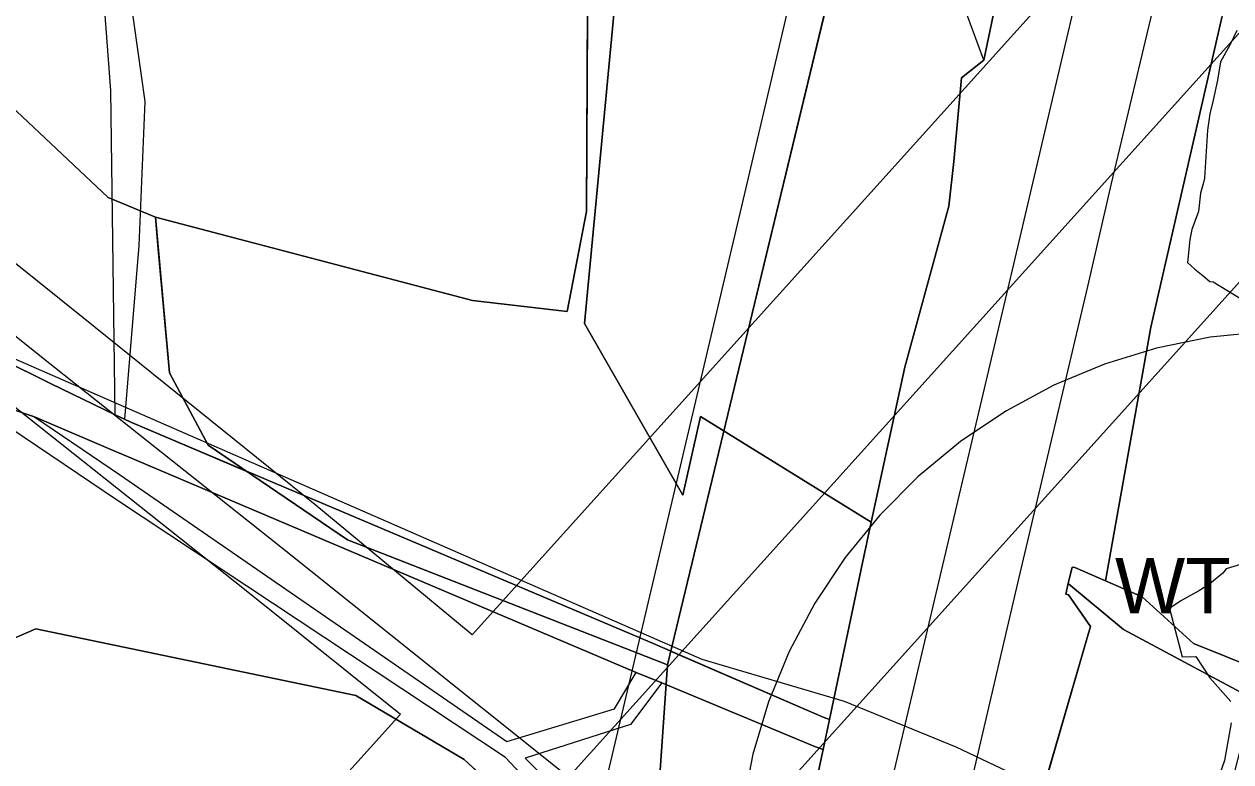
# Model space of a CAD drawing. Extents: x -690419 to -685080, y -987825 to -981190.
# Drawn here: x -687048.1 to -686831.2, y -987168.9 to -987036.3 of the extents above; entities that cross this region are included whole.
import ezdxf

# ---------------------------------------------------------------- set-up
doc = ezdxf.new("R2010")
doc.units = 0
for name, color, linetype in [('BP VTL plynovodu a RS (S)', 7, 'Continuous'), ('BPEJ (S) - hranice', 7, 'Continuous'), ('BPEJ I-II ochrana', 7, 'Continuous'), ('Elektro VN 35 nadzemní (S)', 7, 'Continuous'), ('Elektro VVN 220 nadzemni (S)', 7, 'Continuous'), ('Elektro VVN 400 nadzemni (S)', 7, 'Continuous'), ('OP elektro VN (S)', 7, 'Continuous'), ('OP silnic (S)', 7, 'Continuous'), ('Plochy dopravy silniční DS (S)', 7, 'Continuous'), ('Plochy smíšené nezastavěného území všeobecné MU (S)', 7, 'Continuous'), ('Plochy veřejná prostranství všeobecná PU (S)', 7, 'Continuous'), ('Plochy vodní a vodnich toku WT (S)', 7, 'Continuous'), ('Plochy zemědělské všeobecné AU (S)', 7, 'Continuous'), ('Regulační bloky STABILIZOVANÉ (S)', 7, 'Continuous'), ('Regulační bloky STABILIZOVANÉ (S) TIS', 7, 'Continuous'), ('Regulační kódy STABILIZOVANÉ (S)', 7, 'Continuous'), ('Regulační kódy STABILIZOVANÉ (S) TIS', 7, 'Continuous'), ('Silnice I třídy (S) - osa', 7, 'Continuous'), ('Vodovodní řady přiváděcí (S)', 7, 'Continuous'), ('Záplavové území Q100 (S)', 7, 'Continuous')]:
    doc.layers.add(name, color=color, linetype=linetype)

msp = doc.modelspace()

# ---------------------------------------------------------------- linework, layer by layer
at = {"layer": 'BP VTL plynovodu a RS (S)'}
msp.add_lwpolyline([(-686825.16, -987091.61), (-686834.93, -987092.61), (-686844.56, -987094.55), (-686853.96, -987097.43), (-686863.02, -987101.22), (-686871.67, -987105.88), (-686879.83, -987111.36), (-686887.4, -987117.62), (-686894.33, -987124.59), (-686900.54, -987132.2), (-686905.97, -987140.39), (-686910.58, -987149.07), (-686914.31, -987158.16), (-686917.13, -987167.57), (-686919.02, -987177.21)], dxfattribs=at)
at = {"layer": 'BPEJ (S) - hranice'}
for points in [[(-686936.25, -987205.68), (-686932.5, -987151.5), (-686895.96, -987000), (-686884.5, -986953.5), (-686813.5, -986784), (-686759.5, -986617.5), (-686731, -986478), (-686706, -986383.5), (-686701, -986329.5), (-686707.5, -986301.5), (-686712.5, -986292), (-686755.5, -986225.5)], [(-686813.5, -986784), (-686884.5, -986953.5), (-686895.96, -987000), (-686932.5, -987151.5), (-686990, -987129), (-687015, -987112), (-687022, -987099), (-687024.5, -987071), (-686967.5, -987086), (-686950.5, -987088), (-686947, -987070), (-686946.68, -987000), (-686946.5, -986962), (-686944.5, -986926), (-686934.5, -986889.5), (-686909.77, -986833.6), (-686877, -986759.5), (-686864, -986705.5), (-686840.5, -986534.5)], [(-686944.5, -986926), (-686946.5, -986962), (-686946.68, -987000), (-686947, -987070), (-686950.5, -987088), (-686967.5, -987086), (-687024.5, -987071), (-687033, -987067.5), (-687050.5, -987051), (-687061, -987017.5), (-687063.76, -987000), (-687074.5, -986932)], [(-687074.5, -986932), (-687063.76, -987000), (-687061, -987017.5), (-687050.5, -987051), (-687033, -987067.5), (-687024.5, -987071), (-687022, -987099), (-687015, -987112), (-686990, -987129), (-686932.5, -987151.5), (-686936.25, -987205.68)], [(-687056.5, -987174.58), (-687057.5, -987150), (-687046, -987145), (-686988.5, -987157), (-686969, -987168.5), (-686950, -987186)], [(-686950, -987186), (-686969, -987168.5), (-686988.5, -987157), (-687046, -987145), (-687057.5, -987150), (-687056.5, -987174.58)]]:
    msp.add_lwpolyline(points, dxfattribs=at)
at = {"layer": 'BPEJ I-II ochrana'}
for p, q in [((-687034.07, -986995.24), (-687026.41, -987050.2)), ((-687032.51, -987048.23), (-687036.03, -987001.52)), ((-686902.9, -987028.75), (-686922.36, -987109.44)), ((-686875.61, -987042.77), (-686879.67, -987031.69)), ((-686832.82, -987035.14), (-686845.63, -987090.8)), ((-686879.64, -987045.94), (-686875.61, -987042.77)), ((-686881.02, -987061.02), (-686879.64, -987045.94)), ((-687031.74, -987106.53), (-687032.51, -987048.23)), ((-687026.41, -987050.2), (-687027.49, -987076.11)), ((-686881.88, -987069.03), (-686881.02, -987061.02)), ((-686889.8, -987097.99), (-686881.88, -987069.03)), ((-687023.99, -987076.72), (-687024.5, -987071)), ((-687027.49, -987076.11), (-687030.06, -987107.34)), ((-686845.63, -987090.8), (-686853.73, -987136.42)), ((-687052.41, -987096.45), (-687043.38, -987100.92)), ((-686895.85, -987125.85), (-686889.8, -987097.99)), ((-687043.38, -987100.92), (-687031.74, -987106.53)), ((-687031.33, -987121.96), (-687057.95, -987104.02)), ((-687031.65, -987113.14), (-687046.24, -987106.93)), ((-687046.24, -987106.93), (-687030.96, -987117.29)), ((-687030.06, -987107.34), (-687028.95, -987107.87)), ((-687028.95, -987107.87), (-687008.06, -987116.72)), ((-686922.36, -987109.44), (-686931.91, -987149.04)), ((-687030.67, -987113.56), (-687031.65, -987113.14)), ((-687008.06, -987116.72), (-687015, -987112)), ((-686938.13, -987152.9), (-687030.67, -987113.56)), ((-687030.96, -987117.29), (-686961.37, -987165.28)), ((-686961.61, -987168.17), (-687031.33, -987121.96)), ((-686897.44, -987133.18), (-686895.85, -987125.85)), ((-686903.38, -987161.33), (-686897.44, -987133.18)), ((-686859.75, -987133.91), (-686860.45, -987136.85)), ((-686859.26, -987134.02), (-686859.75, -987133.91)), ((-686853.73, -987136.42), (-686859.26, -987134.02)), ((-686860.45, -987136.85), (-686860.91, -987138.79)), ((-686860.91, -987138.79), (-686860.42, -987138.91)), ((-686860.42, -987138.91), (-686856.46, -987144.62)), ((-686856.46, -987144.62), (-686856.92, -987146.2)), ((-686856.92, -987146.2), (-686865.24, -987174.86)), ((-686931.91, -987149.04), (-686904.48, -987160.91)), ((-686941.97, -987159.4), (-686938.13, -987152.9)), ((-686933.49, -987154.73), (-686939.15, -987162.23)), ((-686905.86, -987166.25), (-686933.49, -987154.73)), ((-686961.37, -987165.28), (-686941.97, -987159.4)), ((-686904.48, -987160.91), (-686903.38, -987161.33)), ((-686939.15, -987162.23), (-686958.07, -987168.28)), ((-686904.51, -987166.69), (-686905.86, -987166.25)), ((-686905.7, -987172.32), (-686904.51, -987166.69)), ((-686946.19, -987184.43), (-686961.61, -987168.17)), ((-686958.07, -987168.28), (-686944.47, -987181.9))]:
    msp.add_line(p, q, dxfattribs=at)
for points in [[(-687024.5, -987071), (-686967.5, -987086), (-686950.5, -987088), (-686947, -987070), (-686946.72, -987007.98)], [(-687015, -987112), (-687022, -987099), (-687023.99, -987076.72)], [(-687051.94, -987147.58), (-687046, -987145), (-687033.03, -987147.71)], [(-687033.03, -987147.71), (-686988.5, -987157), (-686969, -987168.5), (-686958.56, -987178.11)]]:
    msp.add_lwpolyline(points, dxfattribs=at)
at = {"layer": 'Elektro VN 35 nadzemní (S)'}
for points in [[(-687044.68, -987096.41), (-687089.26, -987060.74), (-687180.2, -986988.23), (-687272.01, -986915.09), (-687345.55, -986856.07), (-687424.59, -986793.57), (-687400.71, -986748.73), (-687400.48, -986748.73), (-687400.48, -986748.81)], [(-686842.06, -987257.67), (-686929.31, -987188.46), (-687001.99, -987130.33), (-687044.68, -987096.41)]]:
    msp.add_lwpolyline(points, dxfattribs=at)
at = {"layer": 'Elektro VVN 220 nadzemni (S)'}
msp.add_lwpolyline([(-687032.7, -987263.2), (-686751.15, -986950.62)], dxfattribs=at)
at = {"layer": 'Elektro VVN 400 nadzemni (S)'}
msp.add_lwpolyline([(-687032.7, -987263.2), (-686751.15, -986950.62)], dxfattribs=at)
at = {"layer": 'OP elektro VN (S)'}
for points in [[(-688231.26, -985362.69), (-688140.91, -985333.4), (-688050.6, -985304.66), (-687926.78, -985265.47), (-687889.09, -985253.55), (-687783.25, -985486.14), (-687655.15, -985766.87), (-687464.28, -985986.39), (-687075.22, -986433.52), (-686939.38, -986589.57), (-686741.02, -986817.05), (-686769.51, -986926.18), (-686773.44, -986930.55), (-686967.58, -987146.08), (-686995.86, -987122.7), (-687037.52, -987089.1), (-687083.41, -987052.28), (-687174.55, -986980.54), (-687265.93, -986906.92), (-687339.37, -986847.5), (-687412.5, -986789.56), (-687406.22, -986778.12)], [(-686920.4, -987183.34), (-686799.44, -987049.06), (-686824.96, -987148.74), (-686848.21, -987239.29), (-686920.4, -987183.34)], [(-687050.91, -987104.23), (-687050.9, -987104.24), (-687008.22, -987138.15), (-686980.45, -987160.36)], [(-686980.45, -987160.36), (-687229.98, -987437.34)]]:
    msp.add_lwpolyline(points, dxfattribs=at)
at = {"layer": 'OP silnic (S)'}
msp.add_lwpolyline([(-686770.45, -986218.55), (-686752.96, -986267.72), (-686743.7, -986299.55), (-686737.27, -986326.53), (-686732.73, -986353.86), (-686729.97, -986381.55), (-686728.94, -986408.48), (-686729.49, -986439.6), (-686731.6, -986462.05), (-686734.79, -986486.63), (-686739.21, -986508.83), (-686746.39, -986537.2), (-686755.51, -986566.52), (-686766.32, -986596.72), (-686817.81, -986728.15), (-686854.98, -986826.72), (-686855.91, -986829.4), (-686880.1, -986906.53), (-686880.96, -986909.61), (-686900.81, -986990.65), (-686918.72, -987067.01), (-686954.7, -987219.72)], dxfattribs=at)
at = {"layer": 'Plochy dopravy silniční DS (S)'}
for p, q in [((-686875.61, -987042.77), (-686873.93, -987034.78)), ((-686832.82, -987035.14), (-686845.63, -987090.8)), ((-686879.64, -987045.94), (-686875.61, -987042.77)), ((-686881.02, -987061.02), (-686879.64, -987045.94)), ((-686881.88, -987069.03), (-686881.02, -987061.02)), ((-686889.8, -987097.99), (-686881.88, -987069.03)), ((-686845.63, -987090.8), (-686853.73, -987136.42)), ((-686895.85, -987125.85), (-686889.8, -987097.99)), ((-686897.44, -987133.18), (-686895.85, -987125.85)), ((-686903.38, -987161.33), (-686897.44, -987133.18)), ((-686859.75, -987133.91), (-686860.45, -987136.85)), ((-686859.26, -987134.02), (-686859.75, -987133.91)), ((-686853.73, -987136.42), (-686859.26, -987134.02)), ((-686860.45, -987136.85), (-686860.91, -987138.79)), ((-686860.91, -987138.79), (-686860.42, -987138.91)), ((-686860.42, -987138.91), (-686856.46, -987144.62)), ((-686856.46, -987144.62), (-686856.92, -987146.2)), ((-686856.92, -987146.2), (-686865.24, -987174.86)), ((-686904.51, -987166.69), (-686903.38, -987161.33)), ((-686905.7, -987172.32), (-686904.51, -987166.69))]:
    msp.add_line(p, q, dxfattribs=at)
at = {"layer": 'Plochy smíšené nezastavěného území všeobecné MU (S)'}
for points in [[(-686851.66, -986943.12), (-686861.43, -986982.38), (-686868.4, -987010.49), (-686871.3, -987022.21), (-686873.93, -987034.78), (-686875.61, -987042.77), (-686879.64, -987045.94), (-686881.02, -987061.02), (-686881.88, -987069.03), (-686889.8, -987097.99), (-686895.85, -987125.85), (-686926.56, -987106.84), (-686929.71, -987120.98), (-686947.38, -987090.16), (-686941.23, -987025.06), (-686941.32, -987008.49), (-686948.57, -987004.84), (-686936.47, -986938.56)], [(-686797.85, -987163.81), (-686837.96, -987147.68), (-686847.14, -987139.28), (-686853.73, -987136.42), (-686845.63, -987090.8), (-686832.82, -987035.14), (-686831.93, -987033.05), (-686831.23, -987029.88), (-686833.48, -987027.69), (-686832.07, -987023.08), (-686831.44, -987021.02), (-686827.56, -987021.98)], [(-687052.28, -987175.23), (-687058.33, -987146.42), (-687059.69, -987125.65), (-687057.95, -987104.02), (-687055.46, -987103.82), (-687046.24, -987106.93), (-687031.65, -987113.14), (-687030.67, -987113.56), (-686938.13, -987152.9), (-686933.49, -987154.73), (-686905.86, -987166.25), (-686904.51, -987166.69), (-686905.7, -987172.32)], [(-686865.24, -987174.86), (-686856.92, -987146.2), (-686856.46, -987144.62), (-686860.42, -987138.91), (-686860.91, -987138.79), (-686860.45, -987136.85), (-686860.02, -987137.21), (-686850.53, -987145.14), (-686828.6, -987156.89), (-686805.1, -987164.6), (-686803.84, -987177.06)]]:
    msp.add_lwpolyline(points, dxfattribs=at)
at = {"layer": 'Plochy veřejná prostranství všeobecná PU (S)'}
for p, q in [((-687052.41, -987096.45), (-687043.38, -987100.92)), ((-687043.38, -987100.92), (-687031.74, -987106.53)), ((-687046.24, -987106.93), (-687055.46, -987103.82)), ((-687031.65, -987113.14), (-687046.24, -987106.93)), ((-687031.74, -987106.53), (-687030.06, -987107.34)), ((-687030.06, -987107.34), (-687028.95, -987107.87)), ((-687028.95, -987107.87), (-686935.6, -987147.41)), ((-687030.67, -987113.56), (-687031.65, -987113.14)), ((-686938.13, -987152.9), (-687030.67, -987113.56)), ((-686935.6, -987147.41), (-686933.38, -987148.4)), ((-686933.38, -987148.4), (-686904.48, -987160.91)), ((-686933.49, -987154.73), (-686938.13, -987152.9)), ((-686905.86, -987166.25), (-686933.49, -987154.73)), ((-686904.48, -987160.91), (-686903.38, -987161.33)), ((-686903.38, -987161.33), (-686904.51, -987166.69)), ((-686904.51, -987166.69), (-686905.86, -987166.25))]:
    msp.add_line(p, q, dxfattribs=at)
at = {"layer": 'Plochy vodní a vodnich toku WT (S)'}
msp.add_lwpolyline([(-686860.45, -987136.85), (-686859.75, -987133.91), (-686859.26, -987134.02), (-686853.73, -987136.42), (-686847.14, -987139.28), (-686837.96, -987147.68), (-686797.85, -987163.81), (-686800.17, -987175.43), (-686803.84, -987177.06), (-686805.1, -987164.6), (-686828.6, -987156.89), (-686850.53, -987145.14), (-686860.02, -987137.21)], close=True, dxfattribs=at)
at = {"layer": 'Plochy zemědělské všeobecné AU (S)'}
msp.add_lwpolyline([(-686936.47, -986938.56), (-686948.57, -987004.84), (-686941.32, -987008.49), (-686941.23, -987025.06), (-686947.38, -987090.16), (-686929.71, -987120.98), (-686926.56, -987106.84), (-686895.85, -987125.85), (-686897.44, -987133.18), (-686903.38, -987161.33), (-686904.48, -987160.91), (-686933.38, -987148.4), (-686935.6, -987147.41), (-687028.95, -987107.87), (-687030.06, -987107.34), (-687031.74, -987106.53), (-687043.38, -987100.92), (-687052.41, -987096.45), (-687057.51, -987088.37), (-687064.71, -987049.91), (-687070.74, -987007.79), (-687072.43, -986974.16), (-687079.35, -986943.19)], dxfattribs=at)
at = {"layer": 'Regulační bloky STABILIZOVANÉ (S)'}
for p, q in [((-686875.61, -987042.77), (-686873.93, -987034.78)), ((-686832.82, -987035.14), (-686845.63, -987090.8)), ((-686879.64, -987045.94), (-686875.61, -987042.77)), ((-686881.02, -987061.02), (-686879.64, -987045.94)), ((-686881.88, -987069.03), (-686881.02, -987061.02)), ((-686889.8, -987097.99), (-686881.88, -987069.03)), ((-686845.63, -987090.8), (-686853.73, -987136.42)), ((-687052.41, -987096.45), (-687043.38, -987100.92)), ((-686895.85, -987125.85), (-686889.8, -987097.99)), ((-687043.38, -987100.92), (-687031.74, -987106.53)), ((-687046.24, -987106.93), (-687055.46, -987103.82)), ((-687031.65, -987113.14), (-687046.24, -987106.93)), ((-687031.74, -987106.53), (-687030.06, -987107.34)), ((-687030.06, -987107.34), (-687028.95, -987107.87)), ((-687028.95, -987107.87), (-686935.6, -987147.41)), ((-687030.67, -987113.56), (-687031.65, -987113.14)), ((-686938.13, -987152.9), (-687030.67, -987113.56)), ((-686897.44, -987133.18), (-686895.85, -987125.85)), ((-686903.38, -987161.33), (-686897.44, -987133.18)), ((-686859.75, -987133.91), (-686860.45, -987136.85)), ((-686859.26, -987134.02), (-686859.75, -987133.91)), ((-686853.73, -987136.42), (-686859.26, -987134.02)), ((-686860.45, -987136.85), (-686860.91, -987138.79)), ((-686860.91, -987138.79), (-686860.42, -987138.91)), ((-686860.42, -987138.91), (-686856.46, -987144.62)), ((-686856.46, -987144.62), (-686856.92, -987146.2)), ((-686935.6, -987147.41), (-686933.38, -987148.4)), ((-686856.92, -987146.2), (-686865.24, -987174.86)), ((-686933.38, -987148.4), (-686904.48, -987160.91)), ((-686933.49, -987154.73), (-686938.13, -987152.9)), ((-686905.86, -987166.25), (-686933.49, -987154.73)), ((-686904.48, -987160.91), (-686903.38, -987161.33)), ((-686903.38, -987161.33), (-686904.51, -987166.69)), ((-686904.51, -987166.69), (-686903.38, -987161.33)), ((-686904.51, -987166.69), (-686905.86, -987166.25)), ((-686905.7, -987172.32), (-686904.51, -987166.69))]:
    msp.add_line(p, q, dxfattribs=at)
for points in [[(-686936.47, -986938.56), (-686948.57, -987004.84), (-686941.32, -987008.49), (-686941.23, -987025.06), (-686947.38, -987090.16), (-686929.71, -987120.98), (-686926.56, -987106.84), (-686895.85, -987125.85), (-686897.44, -987133.18), (-686903.38, -987161.33), (-686904.48, -987160.91), (-686933.38, -987148.4), (-686935.6, -987147.41), (-687028.95, -987107.87), (-687030.06, -987107.34), (-687031.74, -987106.53), (-687043.38, -987100.92), (-687052.41, -987096.45), (-687057.51, -987088.37), (-687064.71, -987049.91), (-687070.74, -987007.79), (-687072.43, -986974.16), (-687079.35, -986943.19)], [(-686851.66, -986943.12), (-686861.43, -986982.38), (-686868.4, -987010.49), (-686871.3, -987022.21), (-686873.93, -987034.78), (-686875.61, -987042.77), (-686879.64, -987045.94), (-686881.02, -987061.02), (-686881.88, -987069.03), (-686889.8, -987097.99), (-686895.85, -987125.85), (-686926.56, -987106.84), (-686929.71, -987120.98), (-686947.38, -987090.16), (-686941.23, -987025.06), (-686941.32, -987008.49), (-686948.57, -987004.84), (-686936.47, -986938.56)], [(-686797.85, -987163.81), (-686837.96, -987147.68), (-686847.14, -987139.28), (-686853.73, -987136.42), (-686845.63, -987090.8), (-686832.82, -987035.14), (-686831.93, -987033.05), (-686831.23, -987029.88), (-686833.48, -987027.69), (-686832.07, -987023.08), (-686831.44, -987021.02), (-686827.56, -987021.98)], [(-687052.28, -987175.23), (-687058.33, -987146.42), (-687059.69, -987125.65), (-687057.95, -987104.02), (-687055.46, -987103.82), (-687046.24, -987106.93), (-687031.65, -987113.14), (-687030.67, -987113.56), (-686938.13, -987152.9), (-686933.49, -987154.73), (-686905.86, -987166.25), (-686904.51, -987166.69), (-686905.7, -987172.32)], [(-686865.24, -987174.86), (-686856.92, -987146.2), (-686856.46, -987144.62), (-686860.42, -987138.91), (-686860.91, -987138.79), (-686860.45, -987136.85), (-686860.02, -987137.21), (-686850.53, -987145.14), (-686828.6, -987156.89), (-686805.1, -987164.6), (-686803.84, -987177.06)]]:
    msp.add_lwpolyline(points, dxfattribs=at)
msp.add_lwpolyline([(-686860.45, -987136.85), (-686859.75, -987133.91), (-686859.26, -987134.02), (-686853.73, -987136.42), (-686847.14, -987139.28), (-686837.96, -987147.68), (-686797.85, -987163.81), (-686800.17, -987175.43), (-686803.84, -987177.06), (-686805.1, -987164.6), (-686828.6, -987156.89), (-686850.53, -987145.14), (-686860.02, -987137.21)], close=True, dxfattribs=at)
at = {"layer": 'Regulační bloky STABILIZOVANÉ (S) TIS'}
for p, q in [((-686859.75, -987133.91), (-686860.45, -987136.85)), ((-686859.26, -987134.02), (-686859.75, -987133.91)), ((-686853.73, -987136.42), (-686859.26, -987134.02)), ((-686797.85, -987163.81), (-686837.96, -987147.68))]:
    msp.add_line(p, q, dxfattribs=at)
for points in [[(-686860.45, -987136.85), (-686860.02, -987137.21), (-686850.53, -987145.14), (-686828.6, -987156.89), (-686805.1, -987164.6)], [(-686837.96, -987147.68), (-686847.14, -987139.28), (-686853.73, -987136.42)]]:
    msp.add_lwpolyline(points, dxfattribs=at)
at = {"layer": 'Silnice I třídy (S) - osa'}
for points in [[(-686705.36, -986252.34), (-686695.34, -986286.77), (-686688.23, -986316.63), (-686683.14, -986347.28), (-686680.06, -986378.11), (-686678.92, -986407.97), (-686679.54, -986442.39), (-686681.91, -986467.6), (-686685.42, -986494.74), (-686690.43, -986519.86), (-686698.24, -986550.77), (-686708.08, -986582.39), (-686719.5, -986614.27), (-686771.14, -986746.09), (-686808.2, -986844.37), (-686832.4, -986921.5), (-686852.19, -987002.31), (-686870.04, -987078.45), (-686905.97, -987230.91)], [(-686877.81, -987172.54), (-686869.48, -987136.82), (-686864.95, -987117.54), (-686856.94, -987083.48), (-686852.65, -987064.99), (-686844.4, -987030.22), (-686835.9, -986993.71), (-686828.6, -986962.75)]]:
    msp.add_lwpolyline(points, dxfattribs=at)
at = {"layer": 'Vodovodní řady přiváděcí (S)'}
msp.add_lwpolyline([(-686841.2, -987440.61), (-686848.76, -987439.19), (-686903.68, -987413.37), (-686903.65, -987371.15), (-686859.73, -987176.17), (-686880.57, -987166.29), (-686900.65, -987158.08), (-686926.23, -987150.51), (-687054.99, -987094.27), (-687071.39, -987076.19), (-687071.13, -987074.96)], dxfattribs=at)
at = {"layer": 'Záplavové území Q100 (S)'}
for points in [[(-686830.17, -987037.48), (-686831.32, -987040), (-686833.11, -987043.11), (-686833.63, -987046.37), (-686834.43, -987050), (-686835, -987052.42), (-686835.4, -987055.4), (-686835.98, -987064.02), (-686836.22, -987065), (-686836.69, -987066.69), (-686837.04, -987070), (-686838.25, -987073.25), (-686838.57, -987075), (-686839.02, -987079.16), (-686837.68, -987080.35), (-686836.23, -987081.55), (-686835, -987082.57), (-686834.42, -987082.66), (-686824.59, -987088.66)], [(-686820.78, -987130.84), (-686832.06, -987134.26), (-686832.64, -987135), (-686835, -987136.93), (-686836.85, -987138.15), (-686840.23, -987140), (-686842.25, -987141.38), (-686840, -987150.04), (-686837.49, -987149.99), (-686835, -987153.82), (-686831.21, -987158.11)], [(-686831.17, -987161.92), (-686832.39, -987168.69), (-686833.37, -987171.63)]]:
    msp.add_lwpolyline(points, dxfattribs=at)

# ---------------------------------------------------------------- texts
at = {"layer": 'Regulační kódy STABILIZOVANÉ (S)'}
msp.add_text('WT', height=10, dxfattribs=at).set_placement((-686852.05, -987142.26))
at = {"layer": 'Regulační kódy STABILIZOVANÉ (S) TIS'}
msp.add_text('WT', height=10, dxfattribs=at).set_placement((-686852.05, -987142.26))

doc.saveas('drawing.dxf')
